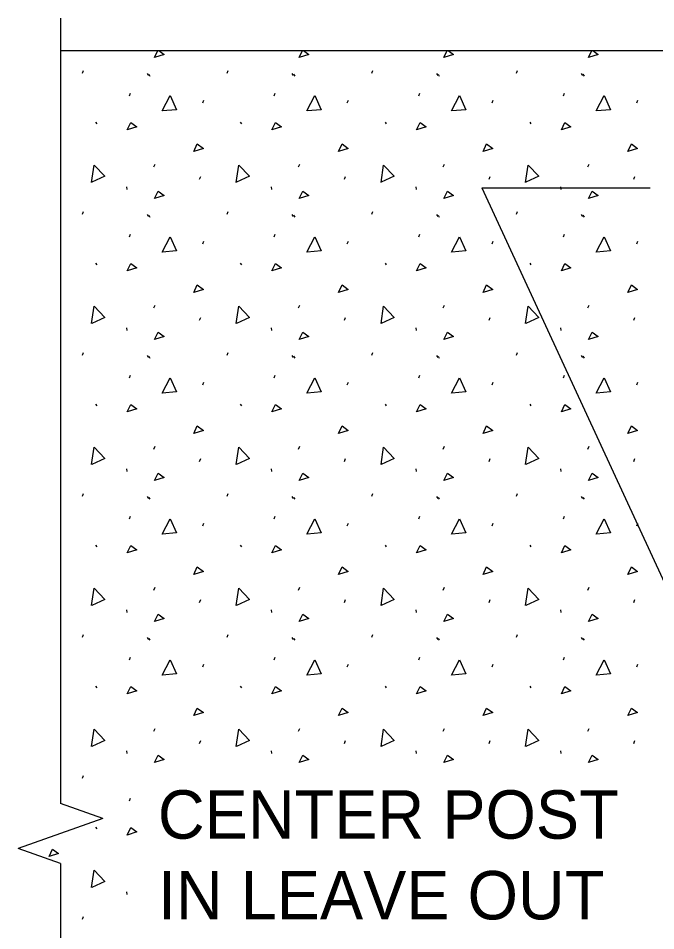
# Model space of a CAD drawing. Extents: x 49991.4 to 50021, y 49987.6 to 50011.4.
# Drawn here: x 50005.275 to 50006.064, y 49991.236 to 49992.367 of the extents above; entities that cross this region are included whole.
import ezdxf

# ---------------------------------------------------------------- set-up
doc = ezdxf.new("R2010")
doc.units = 0
for name, color, linetype in [('Level 1', 7, 'Continuous'), ('Level 2', 7, 'Continuous'), ('Level 3', 7, 'Continuous'), ('Level 6', 7, 'Continuous')]:
    doc.layers.add(name, color=color, linetype=linetype)

msp = doc.modelspace()

# ---------------------------------------------------------------- linework, layer by layer
at = {"layer": 'Level 1'}
for p, q in [((50005.3272, 49992.3269), (50007.655, 49992.3269)), ((50005.4436, 49992.3182), (50005.4478, 49992.3269)), ((50005.6228, 49992.3182), (50005.6269, 49992.3269)), ((50005.8019, 49992.3182), (50005.8061, 49992.3269)), ((50005.9811, 49992.3182), (50005.9852, 49992.3269)), ((50005.3543, 49992.2988), (50005.3558, 49992.3022)), ((50005.4345, 49992.2983), (50005.436, 49992.2961)), ((50005.4365, 49992.2975), (50005.438, 49992.2953)), ((50005.5335, 49992.2988), (50005.535, 49992.3022)), ((50005.6137, 49992.2983), (50005.6152, 49992.2961)), ((50005.6157, 49992.2975), (50005.6172, 49992.2953)), ((50005.7126, 49992.2988), (50005.7141, 49992.3022)), ((50005.7928, 49992.2983), (50005.7943, 49992.2961)), ((50005.7948, 49992.2975), (50005.7963, 49992.2953)), ((50005.8918, 49992.2988), (50005.8933, 49992.3022)), ((50005.972, 49992.2983), (50005.9735, 49992.2961)), ((50005.974, 49992.2975), (50005.9755, 49992.2953)), ((50005.4125, 49992.2707), (50005.414, 49992.2741)), ((50005.5917, 49992.2707), (50005.5932, 49992.2741)), ((50005.7708, 49992.2707), (50005.7723, 49992.2741)), ((50005.95, 49992.2707), (50005.9515, 49992.2741)), ((50005.5033, 49992.2621), (50005.5048, 49992.2655)), ((50005.6824, 49992.2621), (50005.6839, 49992.2655)), ((50005.8616, 49992.2621), (50005.8631, 49992.2655)), ((50006.0407, 49992.2621), (50006.0422, 49992.2655)), ((50005.3707, 49992.2383), (50005.3722, 49992.236)), ((50005.4099, 49992.2286), (50005.4144, 49992.2379)), ((50005.4144, 49992.2379), (50005.4218, 49992.2323)), ((50005.5499, 49992.2383), (50005.5514, 49992.236)), ((50005.5891, 49992.2286), (50005.5935, 49992.2379)), ((50005.5935, 49992.2379), (50005.601, 49992.2323)), ((50005.7291, 49992.2383), (50005.7305, 49992.236)), ((50005.7682, 49992.2286), (50005.7727, 49992.2379)), ((50005.7727, 49992.2379), (50005.7801, 49992.2323)), ((50005.9082, 49992.2383), (50005.9097, 49992.236)), ((50005.9474, 49992.2286), (50005.9518, 49992.2379)), ((50005.9518, 49992.2379), (50005.9593, 49992.2323)), ((50005.4218, 49992.2323), (50005.4099, 49992.2286)), ((50005.601, 49992.2323), (50005.5891, 49992.2286)), ((50005.7801, 49992.2323), (50005.7682, 49992.2286)), ((50005.9593, 49992.2323), (50005.9474, 49992.2286)), ((50005.4429, 49992.1827), (50005.4443, 49992.186)), ((50005.622, 49992.1827), (50005.6235, 49992.186)), ((50005.8012, 49992.1827), (50005.8027, 49992.186)), ((50005.9803, 49992.1827), (50005.9818, 49992.186)), ((50005.4995, 49992.1674), (50005.501, 49992.1707)), ((50005.6787, 49992.1674), (50005.6802, 49992.1707)), ((50005.8579, 49992.1674), (50005.8594, 49992.1707)), ((50006.037, 49992.1674), (50006.0385, 49992.1707)), ((50005.4091, 49992.158), (50005.4094, 49992.1547)), ((50005.5882, 49992.158), (50005.5886, 49992.1547)), ((50005.7674, 49992.158), (50005.7677, 49992.1547)), ((50005.9465, 49992.158), (50005.9469, 49992.1547)), ((50005.3543, 49992.1241), (50005.3558, 49992.1275)), ((50005.5335, 49992.1241), (50005.535, 49992.1275)), ((50005.7126, 49992.1241), (50005.7141, 49992.1275)), ((50005.8918, 49992.1241), (50005.8933, 49992.1275)), ((50005.4345, 49992.1236), (50005.436, 49992.1214)), ((50005.4365, 49992.1228), (50005.438, 49992.1205)), ((50005.6137, 49992.1236), (50005.6152, 49992.1214)), ((50005.6157, 49992.1228), (50005.6172, 49992.1205)), ((50005.7928, 49992.1236), (50005.7943, 49992.1214)), ((50005.7948, 49992.1228), (50005.7963, 49992.1205)), ((50005.972, 49992.1236), (50005.9735, 49992.1214)), ((50005.974, 49992.1228), (50005.9755, 49992.1205)), ((50005.4125, 49992.096), (50005.414, 49992.0993)), ((50005.5033, 49992.0874), (50005.5048, 49992.0908)), ((50005.5917, 49992.096), (50005.5932, 49992.0993)), ((50005.6824, 49992.0874), (50005.6839, 49992.0908)), ((50005.7708, 49992.096), (50005.7723, 49992.0993)), ((50005.8616, 49992.0874), (50005.8631, 49992.0908)), ((50005.95, 49992.096), (50005.9515, 49992.0993)), ((50006.0407, 49992.0874), (50006.0422, 49992.0908)), ((50005.3707, 49992.0635), (50005.3722, 49992.0613)), ((50005.4099, 49992.0538), (50005.4144, 49992.0632)), ((50005.4218, 49992.0576), (50005.4099, 49992.0538)), ((50005.4144, 49992.0632), (50005.4218, 49992.0576)), ((50005.5499, 49992.0635), (50005.5514, 49992.0613)), ((50005.5891, 49992.0538), (50005.5935, 49992.0632)), ((50005.601, 49992.0576), (50005.5891, 49992.0538)), ((50005.5935, 49992.0632), (50005.601, 49992.0576)), ((50005.7291, 49992.0635), (50005.7305, 49992.0613)), ((50005.7682, 49992.0538), (50005.7727, 49992.0632)), ((50005.7801, 49992.0576), (50005.7682, 49992.0538)), ((50005.7727, 49992.0632), (50005.7801, 49992.0576)), ((50005.9082, 49992.0635), (50005.9097, 49992.0613)), ((50005.9474, 49992.0538), (50005.9518, 49992.0632)), ((50005.9593, 49992.0576), (50005.9474, 49992.0538)), ((50005.9518, 49992.0632), (50005.9593, 49992.0576)), ((50005.4429, 49992.008), (50005.4443, 49992.0113)), ((50005.622, 49992.008), (50005.6235, 49992.0113)), ((50005.8012, 49992.008), (50005.8027, 49992.0113)), ((50005.9803, 49992.008), (50005.9818, 49992.0113)), ((50005.4995, 49991.9927), (50005.501, 49991.996)), ((50005.6787, 49991.9927), (50005.6802, 49991.996)), ((50005.8579, 49991.9927), (50005.8594, 49991.996)), ((50006.037, 49991.9927), (50006.0385, 49991.996)), ((50005.4091, 49991.9833), (50005.4094, 49991.9799)), ((50005.5882, 49991.9833), (50005.5886, 49991.9799)), ((50005.7674, 49991.9833), (50005.7677, 49991.9799)), ((50005.9465, 49991.9833), (50005.9469, 49991.9799)), ((50005.3543, 49991.9494), (50005.3558, 49991.9528)), ((50005.4345, 49991.9489), (50005.436, 49991.9467)), ((50005.4365, 49991.9481), (50005.438, 49991.9458)), ((50005.5335, 49991.9494), (50005.535, 49991.9528)), ((50005.6137, 49991.9489), (50005.6152, 49991.9467)), ((50005.6157, 49991.9481), (50005.6172, 49991.9458)), ((50005.7126, 49991.9494), (50005.7141, 49991.9528)), ((50005.7928, 49991.9489), (50005.7943, 49991.9467)), ((50005.7948, 49991.9481), (50005.7963, 49991.9458)), ((50005.8918, 49991.9494), (50005.8933, 49991.9528)), ((50005.972, 49991.9489), (50005.9735, 49991.9467)), ((50005.974, 49991.9481), (50005.9755, 49991.9458)), ((50005.4125, 49991.9213), (50005.414, 49991.9246)), ((50005.5917, 49991.9213), (50005.5932, 49991.9246)), ((50005.7708, 49991.9213), (50005.7723, 49991.9246)), ((50005.95, 49991.9213), (50005.9515, 49991.9246)), ((50005.5033, 49991.9127), (50005.5048, 49991.916)), ((50005.6824, 49991.9127), (50005.6839, 49991.916)), ((50005.8616, 49991.9127), (50005.8631, 49991.916)), ((50006.0407, 49991.9127), (50006.0422, 49991.916)), ((50005.3707, 49991.8888), (50005.3722, 49991.8866)), ((50005.4099, 49991.8791), (50005.4144, 49991.8884)), ((50005.4144, 49991.8884), (50005.4218, 49991.8828)), ((50005.5499, 49991.8888), (50005.5514, 49991.8866)), ((50005.5891, 49991.8791), (50005.5935, 49991.8884)), ((50005.5935, 49991.8884), (50005.601, 49991.8828)), ((50005.7291, 49991.8888), (50005.7305, 49991.8866)), ((50005.7682, 49991.8791), (50005.7727, 49991.8884)), ((50005.7727, 49991.8884), (50005.7801, 49991.8828)), ((50005.9082, 49991.8888), (50005.9097, 49991.8866)), ((50005.9474, 49991.8791), (50005.9518, 49991.8884)), ((50005.9518, 49991.8884), (50005.9593, 49991.8828)), ((50005.4218, 49991.8828), (50005.4099, 49991.8791)), ((50005.601, 49991.8828), (50005.5891, 49991.8791)), ((50005.7801, 49991.8828), (50005.7682, 49991.8791)), ((50005.9593, 49991.8828), (50005.9474, 49991.8791)), ((50005.4429, 49991.8332), (50005.4443, 49991.8366)), ((50005.622, 49991.8332), (50005.6235, 49991.8366)), ((50005.8012, 49991.8332), (50005.8027, 49991.8366)), ((50005.9803, 49991.8332), (50005.9818, 49991.8366)), ((50005.4995, 49991.8179), (50005.501, 49991.8213)), ((50005.6787, 49991.8179), (50005.6802, 49991.8213)), ((50005.8579, 49991.8179), (50005.8594, 49991.8213)), ((50006.037, 49991.8179), (50006.0385, 49991.8213)), ((50005.4091, 49991.8086), (50005.4094, 49991.8052)), ((50005.5882, 49991.8086), (50005.5886, 49991.8052)), ((50005.7674, 49991.8086), (50005.7677, 49991.8052)), ((50005.9465, 49991.8086), (50005.9469, 49991.8052)), ((50005.3543, 49991.7747), (50005.3558, 49991.778)), ((50005.4345, 49991.7742), (50005.436, 49991.7719)), ((50005.5335, 49991.7747), (50005.535, 49991.778)), ((50005.6137, 49991.7742), (50005.6152, 49991.7719)), ((50005.7126, 49991.7747), (50005.7141, 49991.778)), ((50005.7928, 49991.7742), (50005.7943, 49991.7719)), ((50005.8918, 49991.7747), (50005.8933, 49991.778)), ((50005.972, 49991.7742), (50005.9735, 49991.7719)), ((50005.4365, 49991.7733), (50005.438, 49991.7711)), ((50005.6157, 49991.7733), (50005.6172, 49991.7711)), ((50005.7948, 49991.7733), (50005.7963, 49991.7711)), ((50005.974, 49991.7733), (50005.9755, 49991.7711)), ((50005.4125, 49991.7465), (50005.414, 49991.7499)), ((50005.5033, 49991.738), (50005.5048, 49991.7413)), ((50005.5917, 49991.7465), (50005.5932, 49991.7499)), ((50005.6824, 49991.738), (50005.6839, 49991.7413)), ((50005.7708, 49991.7465), (50005.7723, 49991.7499)), ((50005.8616, 49991.738), (50005.8631, 49991.7413)), ((50005.95, 49991.7465), (50005.9515, 49991.7499)), ((50006.0407, 49991.738), (50006.0422, 49991.7413)), ((50005.3707, 49991.7141), (50005.3722, 49991.7118)), ((50005.4099, 49991.7044), (50005.4144, 49991.7137)), ((50005.4218, 49991.7081), (50005.4099, 49991.7044)), ((50005.4144, 49991.7137), (50005.4218, 49991.7081)), ((50005.5499, 49991.7141), (50005.5514, 49991.7118)), ((50005.5891, 49991.7044), (50005.5935, 49991.7137)), ((50005.601, 49991.7081), (50005.5891, 49991.7044)), ((50005.5935, 49991.7137), (50005.601, 49991.7081)), ((50005.7291, 49991.7141), (50005.7305, 49991.7118)), ((50005.7682, 49991.7044), (50005.7727, 49991.7137)), ((50005.7801, 49991.7081), (50005.7682, 49991.7044)), ((50005.7727, 49991.7137), (50005.7801, 49991.7081)), ((50005.9082, 49991.7141), (50005.9097, 49991.7118)), ((50005.9474, 49991.7044), (50005.9518, 49991.7137)), ((50005.9593, 49991.7081), (50005.9474, 49991.7044)), ((50005.9518, 49991.7137), (50005.9593, 49991.7081)), ((50005.4429, 49991.6585), (50005.4443, 49991.6619)), ((50005.622, 49991.6585), (50005.6235, 49991.6619)), ((50005.8012, 49991.6585), (50005.8027, 49991.6619)), ((50005.9803, 49991.6585), (50005.9818, 49991.6619)), ((50005.4995, 49991.6432), (50005.501, 49991.6466)), ((50005.6787, 49991.6432), (50005.6802, 49991.6466)), ((50005.8579, 49991.6432), (50005.8594, 49991.6466)), ((50006.037, 49991.6432), (50006.0385, 49991.6466)), ((50005.4091, 49991.6339), (50005.4094, 49991.6305)), ((50005.5882, 49991.6339), (50005.5886, 49991.6305)), ((50005.7674, 49991.6339), (50005.7677, 49991.6305)), ((50005.9465, 49991.6339), (50005.9469, 49991.6305)), ((50005.3543, 49991.6), (50005.3558, 49991.6033)), ((50005.4345, 49991.5995), (50005.436, 49991.5972)), ((50005.4365, 49991.5986), (50005.438, 49991.5964)), ((50005.5335, 49991.6), (50005.535, 49991.6033)), ((50005.6137, 49991.5995), (50005.6152, 49991.5972)), ((50005.6157, 49991.5986), (50005.6172, 49991.5964)), ((50005.7126, 49991.6), (50005.7141, 49991.6033)), ((50005.7928, 49991.5995), (50005.7943, 49991.5972)), ((50005.7948, 49991.5986), (50005.7963, 49991.5964)), ((50005.8918, 49991.6), (50005.8933, 49991.6033)), ((50005.972, 49991.5995), (50005.9735, 49991.5972)), ((50005.974, 49991.5986), (50005.9755, 49991.5964)), ((50005.4125, 49991.5718), (50005.414, 49991.5752)), ((50005.5917, 49991.5718), (50005.5932, 49991.5752)), ((50005.7708, 49991.5718), (50005.7723, 49991.5752)), ((50005.95, 49991.5718), (50005.9515, 49991.5752)), ((50005.5033, 49991.5632), (50005.5048, 49991.5666)), ((50005.6824, 49991.5632), (50005.6839, 49991.5666)), ((50005.8616, 49991.5632), (50005.8631, 49991.5666)), ((50006.0407, 49991.5632), (50006.0422, 49991.5666)), ((50005.3707, 49991.5394), (50005.3722, 49991.5371)), ((50005.4099, 49991.5297), (50005.4144, 49991.539)), ((50005.4144, 49991.539), (50005.4218, 49991.5334)), ((50005.5499, 49991.5394), (50005.5514, 49991.5371)), ((50005.5891, 49991.5297), (50005.5935, 49991.539)), ((50005.5935, 49991.539), (50005.601, 49991.5334)), ((50005.7291, 49991.5394), (50005.7305, 49991.5371)), ((50005.7682, 49991.5297), (50005.7727, 49991.539)), ((50005.7727, 49991.539), (50005.7801, 49991.5334)), ((50005.9082, 49991.5394), (50005.9097, 49991.5371)), ((50005.9474, 49991.5297), (50005.9518, 49991.539)), ((50005.9518, 49991.539), (50005.9593, 49991.5334)), ((50005.4218, 49991.5334), (50005.4099, 49991.5297)), ((50005.601, 49991.5334), (50005.5891, 49991.5297)), ((50005.7801, 49991.5334), (50005.7682, 49991.5297)), ((50005.9593, 49991.5334), (50005.9474, 49991.5297)), ((50005.4429, 49991.4838), (50005.4443, 49991.4871)), ((50005.622, 49991.4838), (50005.6235, 49991.4871)), ((50005.8012, 49991.4838), (50005.8027, 49991.4871)), ((50005.9803, 49991.4838), (50005.9818, 49991.4871)), ((50005.4995, 49991.4685), (50005.501, 49991.4719)), ((50005.6787, 49991.4685), (50005.6802, 49991.4719)), ((50005.8579, 49991.4685), (50005.8594, 49991.4719)), ((50006.037, 49991.4685), (50006.0385, 49991.4719)), ((50005.4091, 49991.4591), (50005.4094, 49991.4558)), ((50005.5882, 49991.4591), (50005.5886, 49991.4558)), ((50005.7674, 49991.4591), (50005.7677, 49991.4558)), ((50005.9465, 49991.4591), (50005.9469, 49991.4558)), ((50005.3543, 49991.4252), (50005.3558, 49991.4286)), ((50005.4125, 49991.3971), (50005.414, 49991.4004)), ((50005.3707, 49991.3646), (50005.3722, 49991.3624)), ((50005.4099, 49991.3549), (50005.4144, 49991.3643)), ((50005.4218, 49991.3587), (50005.4099, 49991.3549)), ((50005.4144, 49991.3643), (50005.4218, 49991.3587)), ((50005.4091, 49991.2844), (50005.4094, 49991.2811)), ((50005.3543, 49991.2505), (50005.3558, 49991.2539))]:
    msp.add_line(p, q, dxfattribs=at)
for points in [[(50005.4489, 49992.3269), (50005.4555, 49992.322), (50005.4436, 49992.3182)], [(50005.6281, 49992.3269), (50005.6347, 49992.322), (50005.6228, 49992.3182)], [(50005.8072, 49992.3269), (50005.8138, 49992.322), (50005.8019, 49992.3182)], [(50005.9864, 49992.3269), (50005.993, 49992.322), (50005.9811, 49992.3182)], [(50005.4529, 49992.2521), (50005.463, 49992.2711), (50005.4708, 49992.2535), (50005.4533, 49992.2521)], [(50005.6321, 49992.2521), (50005.6421, 49992.2711), (50005.65, 49992.2535), (50005.6325, 49992.2521)], [(50005.8112, 49992.2521), (50005.8213, 49992.2711), (50005.8291, 49992.2535), (50005.8116, 49992.2521)], [(50005.9904, 49992.2521), (50006.0005, 49992.2711), (50006.0083, 49992.2535), (50005.9908, 49992.2521)], [(50005.4922, 49992.2019), (50005.4966, 49992.2112), (50005.5041, 49992.2056), (50005.4922, 49992.2019)], [(50005.6713, 49992.2019), (50005.6758, 49992.2112), (50005.6833, 49992.2056), (50005.6713, 49992.2019)], [(50005.8505, 49992.2019), (50005.8549, 49992.2112), (50005.8624, 49992.2056), (50005.8505, 49992.2019)], [(50006.0296, 49992.2019), (50006.0341, 49992.2112), (50006.0416, 49992.2056), (50006.0296, 49992.2019)], [(50005.3658, 49992.1635), (50005.3687, 49992.1848), (50005.3821, 49992.1711), (50005.3661, 49992.1637)], [(50005.5449, 49992.1635), (50005.5479, 49992.1848), (50005.5612, 49992.1711), (50005.5453, 49992.1637)], [(50005.7241, 49992.1635), (50005.727, 49992.1848), (50005.7404, 49992.1711), (50005.7244, 49992.1637)], [(50005.9032, 49992.1635), (50005.9062, 49992.1848), (50005.9195, 49992.1711), (50005.9036, 49992.1637)], [(50005.4436, 49992.1435), (50005.4481, 49992.1528), (50005.4555, 49992.1472), (50005.4436, 49992.1435)], [(50005.6228, 49992.1435), (50005.6272, 49992.1528), (50005.6347, 49992.1472), (50005.6228, 49992.1435)], [(50005.8019, 49992.1435), (50005.8064, 49992.1528), (50005.8138, 49992.1472), (50005.8019, 49992.1435)], [(50005.9811, 49992.1435), (50005.9855, 49992.1528), (50005.993, 49992.1472), (50005.9811, 49992.1435)], [(50005.4529, 49992.0773), (50005.463, 49992.0963), (50005.4708, 49992.0788), (50005.4533, 49992.0773)], [(50005.6321, 49992.0773), (50005.6421, 49992.0963), (50005.65, 49992.0788), (50005.6325, 49992.0773)], [(50005.8112, 49992.0773), (50005.8213, 49992.0963), (50005.8291, 49992.0788), (50005.8116, 49992.0773)], [(50005.9904, 49992.0773), (50006.0005, 49992.0963), (50006.0083, 49992.0788), (50005.9908, 49992.0773)], [(50005.4922, 49992.0272), (50005.4966, 49992.0365), (50005.5041, 49992.0309), (50005.4922, 49992.0272)], [(50005.6713, 49992.0272), (50005.6758, 49992.0365), (50005.6833, 49992.0309), (50005.6713, 49992.0272)], [(50005.8505, 49992.0272), (50005.8549, 49992.0365), (50005.8624, 49992.0309), (50005.8505, 49992.0272)], [(50006.0296, 49992.0272), (50006.0341, 49992.0365), (50006.0416, 49992.0309), (50006.0296, 49992.0272)], [(50005.3658, 49991.9888), (50005.3687, 49992.0101), (50005.3821, 49991.9963), (50005.3661, 49991.9889)], [(50005.5449, 49991.9888), (50005.5479, 49992.0101), (50005.5612, 49991.9963), (50005.5453, 49991.9889)], [(50005.7241, 49991.9888), (50005.727, 49992.0101), (50005.7404, 49991.9963), (50005.7244, 49991.9889)], [(50005.9032, 49991.9888), (50005.9062, 49992.0101), (50005.9195, 49991.9963), (50005.9036, 49991.9889)], [(50005.4436, 49991.9688), (50005.4481, 49991.9781), (50005.4555, 49991.9725), (50005.4436, 49991.9688)], [(50005.6228, 49991.9688), (50005.6272, 49991.9781), (50005.6347, 49991.9725), (50005.6228, 49991.9688)], [(50005.8019, 49991.9688), (50005.8064, 49991.9781), (50005.8138, 49991.9725), (50005.8019, 49991.9688)], [(50005.9811, 49991.9688), (50005.9855, 49991.9781), (50005.993, 49991.9725), (50005.9811, 49991.9688)], [(50005.4529, 49991.9026), (50005.463, 49991.9216), (50005.4708, 49991.9041), (50005.4533, 49991.9026)], [(50005.6321, 49991.9026), (50005.6421, 49991.9216), (50005.65, 49991.9041), (50005.6325, 49991.9026)], [(50005.8112, 49991.9026), (50005.8213, 49991.9216), (50005.8291, 49991.9041), (50005.8116, 49991.9026)], [(50005.9904, 49991.9026), (50006.0005, 49991.9216), (50006.0083, 49991.9041), (50005.9908, 49991.9026)], [(50005.4922, 49991.8524), (50005.4966, 49991.8618), (50005.5041, 49991.8562), (50005.4922, 49991.8524)], [(50005.6713, 49991.8524), (50005.6758, 49991.8618), (50005.6833, 49991.8562), (50005.6713, 49991.8524)], [(50005.8505, 49991.8524), (50005.8549, 49991.8618), (50005.8624, 49991.8562), (50005.8505, 49991.8524)], [(50006.0296, 49991.8524), (50006.0341, 49991.8618), (50006.0416, 49991.8562), (50006.0296, 49991.8524)], [(50005.3658, 49991.8141), (50005.3687, 49991.8354), (50005.3821, 49991.8216), (50005.3661, 49991.8142)], [(50005.5449, 49991.8141), (50005.5479, 49991.8354), (50005.5612, 49991.8216), (50005.5453, 49991.8142)], [(50005.7241, 49991.8141), (50005.727, 49991.8354), (50005.7404, 49991.8216), (50005.7244, 49991.8142)], [(50005.9032, 49991.8141), (50005.9062, 49991.8354), (50005.9195, 49991.8216), (50005.9036, 49991.8142)], [(50005.4436, 49991.7941), (50005.4481, 49991.8034), (50005.4555, 49991.7978), (50005.4436, 49991.7941)], [(50005.6228, 49991.7941), (50005.6272, 49991.8034), (50005.6347, 49991.7978), (50005.6228, 49991.7941)], [(50005.8019, 49991.7941), (50005.8064, 49991.8034), (50005.8138, 49991.7978), (50005.8019, 49991.7941)], [(50005.9811, 49991.7941), (50005.9855, 49991.8034), (50005.993, 49991.7978), (50005.9811, 49991.7941)], [(50005.4529, 49991.7279), (50005.463, 49991.7469), (50005.4708, 49991.7294), (50005.4533, 49991.7279)], [(50005.6321, 49991.7279), (50005.6421, 49991.7469), (50005.65, 49991.7294), (50005.6325, 49991.7279)], [(50005.8112, 49991.7279), (50005.8213, 49991.7469), (50005.8291, 49991.7294), (50005.8116, 49991.7279)], [(50005.9904, 49991.7279), (50006.0005, 49991.7469), (50006.0083, 49991.7294), (50005.9908, 49991.7279)], [(50005.4922, 49991.6777), (50005.4966, 49991.6871), (50005.5041, 49991.6815), (50005.4922, 49991.6777)], [(50005.6713, 49991.6777), (50005.6758, 49991.6871), (50005.6833, 49991.6815), (50005.6713, 49991.6777)], [(50005.8505, 49991.6777), (50005.8549, 49991.6871), (50005.8624, 49991.6815), (50005.8505, 49991.6777)], [(50006.0296, 49991.6777), (50006.0341, 49991.6871), (50006.0416, 49991.6815), (50006.0296, 49991.6777)], [(50005.3658, 49991.6394), (50005.3687, 49991.6607), (50005.3821, 49991.6469), (50005.3661, 49991.6395)], [(50005.5449, 49991.6394), (50005.5479, 49991.6607), (50005.5612, 49991.6469), (50005.5453, 49991.6395)], [(50005.7241, 49991.6394), (50005.727, 49991.6607), (50005.7404, 49991.6469), (50005.7244, 49991.6395)], [(50005.9032, 49991.6394), (50005.9062, 49991.6607), (50005.9195, 49991.6469), (50005.9036, 49991.6395)], [(50005.4436, 49991.6194), (50005.4481, 49991.6287), (50005.4555, 49991.6231), (50005.4436, 49991.6194)], [(50005.6228, 49991.6194), (50005.6272, 49991.6287), (50005.6347, 49991.6231), (50005.6228, 49991.6194)], [(50005.8019, 49991.6194), (50005.8064, 49991.6287), (50005.8138, 49991.6231), (50005.8019, 49991.6194)], [(50005.9811, 49991.6194), (50005.9855, 49991.6287), (50005.993, 49991.6231), (50005.9811, 49991.6194)], [(50005.4529, 49991.5532), (50005.463, 49991.5722), (50005.4708, 49991.5547), (50005.4533, 49991.5532)], [(50005.6321, 49991.5532), (50005.6421, 49991.5722), (50005.65, 49991.5547), (50005.6325, 49991.5532)], [(50005.8112, 49991.5532), (50005.8213, 49991.5722), (50005.8291, 49991.5547), (50005.8116, 49991.5532)], [(50005.9904, 49991.5532), (50006.0005, 49991.5722), (50006.0083, 49991.5547), (50005.9908, 49991.5532)], [(50005.4922, 49991.503), (50005.4966, 49991.5123), (50005.5041, 49991.5067), (50005.4922, 49991.503)], [(50005.6713, 49991.503), (50005.6758, 49991.5123), (50005.6833, 49991.5067), (50005.6713, 49991.503)], [(50005.8505, 49991.503), (50005.8549, 49991.5123), (50005.8624, 49991.5067), (50005.8505, 49991.503)], [(50006.0296, 49991.503), (50006.0341, 49991.5123), (50006.0416, 49991.5067), (50006.0296, 49991.503)], [(50005.3658, 49991.4646), (50005.3687, 49991.486), (50005.3821, 49991.4722), (50005.3661, 49991.4648)], [(50005.5449, 49991.4646), (50005.5479, 49991.486), (50005.5612, 49991.4722), (50005.5453, 49991.4648)], [(50005.7241, 49991.4646), (50005.727, 49991.486), (50005.7404, 49991.4722), (50005.7244, 49991.4648)], [(50005.9032, 49991.4646), (50005.9062, 49991.486), (50005.9195, 49991.4722), (50005.9036, 49991.4648)], [(50005.4436, 49991.4446), (50005.4481, 49991.454), (50005.4555, 49991.4484), (50005.4436, 49991.4446)], [(50005.6228, 49991.4446), (50005.6272, 49991.454), (50005.6347, 49991.4484), (50005.6228, 49991.4446)], [(50005.8019, 49991.4446), (50005.8064, 49991.454), (50005.8138, 49991.4484), (50005.8019, 49991.4446)], [(50005.9811, 49991.4446), (50005.9855, 49991.454), (50005.993, 49991.4484), (50005.9811, 49991.4446)], [(50005.313, 49991.3283), (50005.3175, 49991.3376), (50005.3249, 49991.332), (50005.313, 49991.3283)], [(50005.3658, 49991.2899), (50005.3687, 49991.3112), (50005.3821, 49991.2974), (50005.3661, 49991.29)]]:
    msp.add_lwpolyline(points, dxfattribs=at)
at = {"layer": 'Level 3'}
for q in [(50006.1711, 49991.4594), (50006.0576, 49992.157)]:
    msp.add_line((50005.8488, 49992.157), q, dxfattribs=at)
at = {"layer": 'Level 6'}
for p, q in [((50005.3272, 49992.3669), (50005.3272, 49991.5129)), ((50005.3272, 49991.5129), (50005.3272, 49991.394)), ((50005.3796, 49991.3755), (50005.3272, 49991.394)), ((50005.3796, 49991.3755), (50005.3272, 49991.3569)), ((50005.3272, 49991.3569), (50005.2749, 49991.3384)), ((50005.3272, 49991.3198), (50005.2749, 49991.3384)), ((50005.3272, 49991.3198), (50005.3272, 49991.2019))]:
    msp.add_line(p, q, dxfattribs=at)

# ---------------------------------------------------------------- texts
at = {"layer": 'Level 2'}
for s, p in [('CENTER POST', (50005.4478, 49991.3504)), ('IN LEAVE OUT', (50005.4478, 49991.2504))]:
    msp.add_text(s, height=0.06, dxfattribs=at).set_placement(p)

doc.saveas('drawing.dxf')
